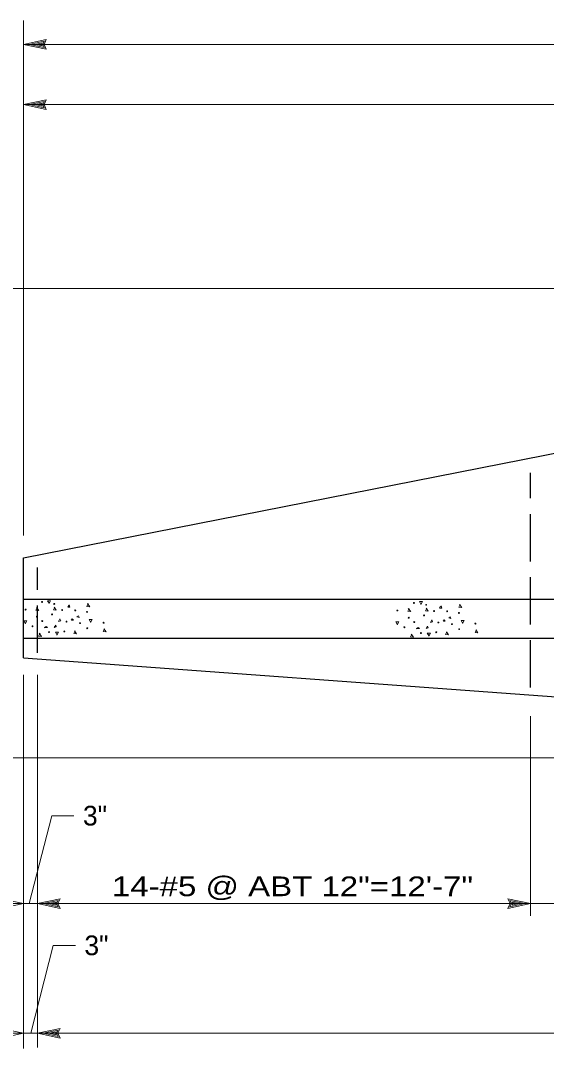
# Model space of a CAD drawing. Extents: x -22.3 to 19.7, y -11.8 to 18.2.
# Drawn here: x -17.11 to -13.77, y -0.22 to 6.3 of the extents above; entities that cross this region are included whole.
import ezdxf
from ezdxf.enums import TextEntityAlignment as Align

# ---------------------------------------------------------------- set-up
doc = ezdxf.new("R2010")
doc.units = 0
doc.header["$LTSCALE"] = 0.05
doc.linetypes.add('LONG_DASHED', pattern=[7.5, 6, -1.5])
doc.layers.add('1', color=7, linetype='Continuous', lineweight=13)
doc.layers.add('2', color=7, linetype='Continuous', lineweight=13)

msp = doc.modelspace()

# ---------------------------------------------------------------- linework, layer by layer
at = {"layer": '1'}
for p, q in [((-17.08742, 3.03631), (-17.08742, 6.29931)), ((-17.08742, 6.14831), (-16.94342, 6.17931)), ((-17.08742, 6.14831), (-8.42042, 6.14831)), ((-17.08742, 6.14831), (-16.94342, 6.11731)), ((-17.05042, 6.14831), (-16.95642, 6.16831)), ((-17.05042, 6.14831), (-16.95642, 6.12831)), ((-17.01442, 6.14831), (-16.96942, 6.15831)), ((-17.01442, 6.14831), (-16.96942, 6.13931)), ((-16.96942, 6.15831), (-16.97342, 6.14831)), ((-16.97342, 6.14831), (-16.96942, 6.13931)), ((-16.95642, 6.16831), (-16.96542, 6.14831)), ((-16.96542, 6.14831), (-16.95642, 6.12831)), ((-17.08742, 5.76631), (-16.94342, 5.79731)), ((-17.08742, 5.76631), (-8.42042, 5.76631)), ((-17.08742, 5.76631), (-16.94342, 5.73531)), ((-17.05042, 5.76631), (-16.95642, 5.78631)), ((-17.05042, 5.76631), (-16.95642, 5.74631)), ((-17.01442, 5.76631), (-16.96942, 5.77631)), ((-17.01442, 5.76631), (-16.96942, 5.75731)), ((-16.96942, 5.77631), (-16.97342, 5.76631)), ((-16.97342, 5.76631), (-16.96942, 5.75731)), ((-16.95642, 5.78631), (-16.96542, 5.76631)), ((-16.96542, 5.76631), (-16.95642, 5.74631)), ((-8.91642, 4.60131), (-18.84342, 4.60131)), ((-17.08742, 2.15131), (-17.08742, -0.21569)), ((-16.99942, 2.15131), (-16.99942, -0.20969)), ((-13.87442, 1.89131), (-13.87442, 0.62531)), ((-8.91642, 1.62731), (-18.86742, 1.62731)), ((-17.08742, 0.70231), (-17.23142, 0.73331)), ((-16.99942, 0.70231), (-16.85542, 0.73331)), ((-16.96242, 0.70231), (-16.86842, 0.72231)), ((-16.86842, 0.72231), (-16.87742, 0.70231)), ((-13.87442, 0.70231), (-14.01842, 0.73331)), ((-13.91142, 0.70231), (-14.00542, 0.72231)), ((-13.99642, 0.70231), (-14.00542, 0.72231)), ((-17.08742, 0.70231), (-17.23142, 0.67131)), ((-16.99942, 0.70231), (-16.85542, 0.67131)), ((-16.96242, 0.70231), (-16.86842, 0.68231)), ((-16.92642, 0.70231), (-16.88142, 0.71231)), ((-16.92642, 0.70231), (-16.88142, 0.69331)), ((-16.88142, 0.71231), (-16.88542, 0.70231)), ((-16.88542, 0.70231), (-16.88142, 0.69331)), ((-16.87742, 0.70231), (-16.86842, 0.68231)), ((-13.87442, 0.70231), (-14.01842, 0.67131)), ((-13.91142, 0.70231), (-14.00542, 0.68231)), ((-14.00542, 0.68231), (-13.99642, 0.70231)), ((-13.94742, 0.70231), (-13.99242, 0.71131)), ((-13.98842, 0.70231), (-13.99242, 0.71131)), ((-13.94742, 0.70231), (-13.99242, 0.69231)), ((-13.99242, 0.69231), (-13.98842, 0.70231)), ((-17.08742, -0.11969), (-17.23142, -0.08869)), ((-17.08742, -0.11969), (-17.23142, -0.15069)), ((-17.07842, -0.11969), (-16.99042, -0.11969)), ((-16.99942, -0.11969), (-16.85542, -0.08869)), ((-16.99942, -0.11969), (-16.85542, -0.15069)), ((-16.96242, -0.11969), (-16.86842, -0.09969)), ((-16.96242, -0.11969), (-16.86842, -0.13969)), ((-16.92642, -0.11969), (-16.88142, -0.10969)), ((-16.92642, -0.11969), (-16.88142, -0.12869)), ((-16.88142, -0.10969), (-16.88542, -0.11969)), ((-16.88542, -0.11969), (-16.88142, -0.12869)), ((-16.86842, -0.09969), (-16.87742, -0.11969)), ((-16.87742, -0.11969), (-16.86842, -0.13969))]:
    msp.add_line(p, q, dxfattribs=at)
at = {"layer": '1', "linetype": 'LONG_DASHED', "lineweight": 25}
for p, q in [((-13.87442, 2.07131), (-13.87442, 3.43331)), ((-16.99942, 2.29131), (-16.99942, 2.83331))]:
    msp.add_line(p, q, dxfattribs=at)
at = {"layer": '1', "lineweight": 25}
for p, q in [((-17.08742, 2.63231), (-10.43942, 2.63231)), ((-17.08742, 2.38431), (-6.38842, 2.38431)), ((-17.08742, 2.26031), (-8.42042, 1.62731))]:
    msp.add_line(p, q, dxfattribs=at)
at = {"layer": '1'}
for points in [[(-16.94342, 6.17931), (-16.95742, 6.14831), (-16.94342, 6.11731)], [(-16.94342, 5.79731), (-16.95742, 5.76631), (-16.94342, 5.73531)], [(-17.05042, 0.70231), (-16.90842, 1.25931), (-16.76742, 1.25931)], [(-16.85542, 0.73331), (-16.86942, 0.70231), (-16.85542, 0.67131)], [(-14.01842, 0.67131), (-14.00442, 0.70231), (-14.01842, 0.73331)], [(-18.23142, 0.70231), (-17.08742, 0.70231), (-16.99942, 0.70231), (-13.87442, 0.70231), (-13.61742, 0.70231), (-12.88542, 0.70231), (-12.61242, 0.70231), (-11.61942, 0.70231), (-11.37642, 0.70231), (-10.61342, 0.70231), (-10.35942, 0.70231), (-9.37342, 0.70231), (-9.22442, 0.70231), (-8.48642, 0.70231), (-8.41442, 0.70231), (-7.89942, 0.70231)], [(-17.04142, -0.11969), (-16.89942, 0.43731), (-16.75842, 0.43731)], [(-18.20842, -0.11969), (-17.08742, -0.11969), (-16.99942, -0.11969), (-9.35942, -0.11969), (-9.22942, -0.11969), (-8.48642, -0.11969), (-8.42042, -0.11969), (-7.80142, -0.11969)], [(-16.85542, -0.08869), (-16.86942, -0.11969), (-16.85542, -0.15069)]]:
    msp.add_lwpolyline(points, dxfattribs=at)
at = {"layer": '1', "lineweight": 25}
msp.add_lwpolyline([(-17.08742, 2.26031), (-17.08742, 2.89431), (-8.41142, 4.60231)], dxfattribs=at)
at = {"layer": '2'}
for p, q in [((-16.80742, 2.58431), (-16.79742, 2.59331)), ((-14.45142, 2.57831), (-14.44142, 2.58731))]:
    msp.add_line(p, q, dxfattribs=at)
for points in [[(-16.92542, 2.60631), (-16.93442, 2.62231), (-16.91542, 2.62231), (-16.92542, 2.60431)], [(-14.56942, 2.60031), (-14.57842, 2.61631), (-14.55942, 2.61631), (-14.56942, 2.59831)], [(-17.00042, 2.57931), (-17.00942, 2.56131), (-16.99042, 2.56031), (-17.00542, 2.57931)], [(-16.88842, 2.58131), (-16.89742, 2.56331), (-16.87942, 2.56131), (-16.89242, 2.58131)], [(-16.79742, 2.59531), (-16.79342, 2.58131), (-16.80742, 2.58131)], [(-16.67742, 2.60431), (-16.68642, 2.58631), (-16.66742, 2.58431), (-16.68142, 2.60431)], [(-14.64442, 2.57331), (-14.65342, 2.55531), (-14.63442, 2.55431), (-14.64942, 2.57331)], [(-14.53242, 2.57531), (-14.54142, 2.55731), (-14.52342, 2.55531), (-14.53642, 2.57531)], [(-14.44142, 2.58931), (-14.43742, 2.57531), (-14.45142, 2.57531)], [(-14.32142, 2.59831), (-14.33042, 2.58031), (-14.31142, 2.57831), (-14.32542, 2.59831)], [(-17.07642, 2.47931), (-17.08542, 2.49431), (-17.06542, 2.49431), (-17.07642, 2.47631)], [(-16.78442, 2.49831), (-16.77842, 2.50731), (-16.77142, 2.49831), (-16.78242, 2.49831)], [(-16.74842, 2.52231), (-16.73942, 2.52531), (-16.73542, 2.51631), (-16.74842, 2.52031)], [(-16.66242, 2.48731), (-16.67142, 2.50231), (-16.65142, 2.50231), (-16.66242, 2.48331)], [(-14.72042, 2.47331), (-14.72942, 2.48831), (-14.70942, 2.48831), (-14.72042, 2.47031)], [(-14.42842, 2.49231), (-14.42242, 2.50131), (-14.41542, 2.49231), (-14.42642, 2.49231)], [(-14.39242, 2.51631), (-14.38342, 2.51931), (-14.37942, 2.51031), (-14.39242, 2.51431)], [(-14.30642, 2.48131), (-14.31542, 2.49631), (-14.29542, 2.49631), (-14.30642, 2.47731)], [(-16.98242, 2.41631), (-16.99142, 2.39831), (-16.97242, 2.39631), (-16.98742, 2.41631)], [(-16.95242, 2.45231), (-16.94342, 2.45831), (-16.93442, 2.45231), (-16.95642, 2.44931)], [(-16.87642, 2.40731), (-16.88542, 2.42231), (-16.86542, 2.42231), (-16.87642, 2.40331)], [(-16.76042, 2.43131), (-16.76942, 2.41331), (-16.75142, 2.41131), (-16.76442, 2.43131)], [(-16.57342, 2.44431), (-16.58242, 2.42631), (-16.56442, 2.42531), (-16.57842, 2.44431)], [(-14.59642, 2.44631), (-14.58742, 2.45231), (-14.57842, 2.44631), (-14.60042, 2.44331)], [(-14.52042, 2.40131), (-14.52942, 2.41631), (-14.50942, 2.41631), (-14.52042, 2.39731)], [(-14.40442, 2.42531), (-14.41342, 2.40731), (-14.39542, 2.40531), (-14.40842, 2.42531)], [(-14.21742, 2.43831), (-14.22642, 2.42031), (-14.20842, 2.41931), (-14.22242, 2.43831)], [(-14.62642, 2.41031), (-14.63542, 2.39231), (-14.61642, 2.39031), (-14.63142, 2.41031)]]:
    msp.add_lwpolyline(points, dxfattribs=at)
for points in [[(-16.86542, 2.49031), (-16.85642, 2.50731), (-16.85142, 2.49531)], [(-14.50942, 2.48431), (-14.50042, 2.50131), (-14.49542, 2.48931)], [(-16.89242, 2.45231), (-16.88342, 2.46731), (-16.87942, 2.45631)], [(-14.53642, 2.44631), (-14.52742, 2.46131), (-14.52342, 2.45031)]]:
    msp.add_lwpolyline(points, close=True, dxfattribs=at)
for centre in [(-16.96947, 2.61414), (-14.61347, 2.60814), (-17.07432, 2.56599), (-16.89252, 2.60199), (-16.84257, 2.56284), (-16.75932, 2.56104), (-16.68507, 2.55069), (-14.71832, 2.55999), (-14.53652, 2.59599), (-14.48657, 2.55684), (-14.40332, 2.55504), (-14.32907, 2.54469), (-17.00277, 2.52054), (-16.96812, 2.49309), (-16.90602, 2.53539), (-16.81512, 2.48994), (-16.72872, 2.47959), (-16.58022, 2.48274), (-14.64677, 2.51454), (-14.61212, 2.48709), (-14.55002, 2.52939), (-14.45912, 2.48394), (-14.37272, 2.47359), (-14.22422, 2.47674), (-17.03022, 2.45979), (-16.92582, 2.42334), (-16.82862, 2.42784), (-16.68327, 2.44764), (-14.67422, 2.45379), (-14.56982, 2.41734), (-14.47262, 2.42184), (-14.32727, 2.44164)]:
    msp.add_circle(centre, 0.00293, dxfattribs=at)

# ---------------------------------------------------------------- texts
at = {"layer": '1'}
for p in [(-16.71042, 1.19731), (-16.70142, 0.37531)]:
    msp.add_text('3"', height=0.125, dxfattribs=at).set_placement(p)
at = {"layer": '1', "width": 1.25}
msp.add_text('14-#5 @ ABT 12"=12\'-7"', height=0.125, dxfattribs=at).set_placement((-15.38292, 0.74931), align=Align.CENTER)

doc.saveas('drawing.dxf')
